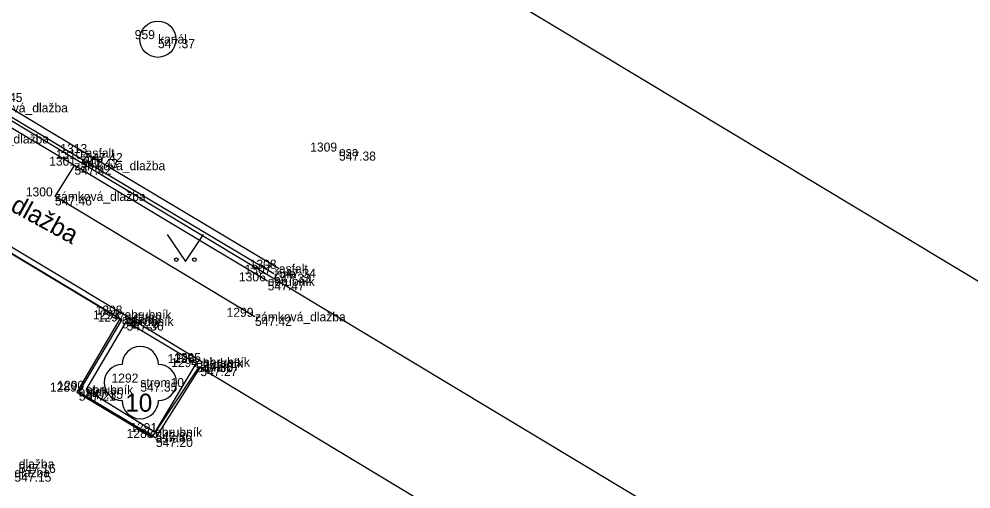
# Model space of a CAD drawing. Extents: x -528274 to -527531, y -1079304 to -1078580.
# Drawn here: x -527787.93 to -527761.62, y -1079117.99 to -1079104.99 of the extents above; entities that cross this region are included whole.
import ezdxf

# ---------------------------------------------------------------- set-up
doc = ezdxf.new("R2010")
doc.units = 0
for name, color, linetype in [('BOD_CISLO', 7, 'Continuous'), ('BOD_KOD', 7, 'Continuous'), ('BOD_VYSKA', 7, 'Continuous'), ('BOD_ZNACKA', 7, 'Continuous'), ('g_kanalizace', 7, 'Continuous'), ('g_komunikace', 7, 'Continuous'), ('g_obrubník', 7, 'Continuous'), ('g_vegetace', 7, 'Continuous'), ('g_zpevněná plocha', 7, 'Continuous'), ('katastrální mapa', 7, 'Continuous'), ('Level 1', 7, 'Continuous'), ('Level 26', 7, 'Continuous')]:
    doc.layers.add(name, color=color, linetype=linetype)

# ---------------------------------------------------------------- blocks, each defined once
blk = doc.blocks.new('6.200')
at = {"layer": 'BOD_CISLO'}
blk.add_circle((0, 0), 0.1, dxfattribs=at)
blk = doc.blocks.new('3.130')
at = {"layer": 'BOD_CISLO'}
blk.add_circle((0, 0), 0.0001, dxfattribs=at)
for centre, start, end in [((0, 0.1), 0, 180), ((-0.1, 0), 90, 270), ((0.1, 0), 270, 90), ((0, -0.1), 180, 360)]:
    blk.add_arc(centre, 0.1, start, end, dxfattribs=at)
blk = doc.blocks.new('3.140')
at = {"layer": 'BOD_CISLO'}
blk.add_lwpolyline([(-0.1, 0.15), (0, 0), (0.1, 0.15)], dxfattribs=at)
for centre in [(-0.05, 0.01), (0.05, 0.01)]:
    blk.add_circle(centre, 0.01, dxfattribs=at)

msp = doc.modelspace()

# ---------------------------------------------------------------- linework, layer by layer
at = {"layer": 'BOD_ZNACKA'}
for p, q in [((-527784.09, -1079105.55), (-527784.09, -1079105.55)), ((-527786.09, -1079108.7), (-527786.09, -1079108.7)), ((-527779.09, -1079108.66), (-527779.09, -1079108.66)), ((-527786.4, -1079109.05), (-527786.4, -1079109.05)), ((-527786.22, -1079108.86), (-527786.22, -1079108.86)), ((-527786.94, -1079109.9), (-527786.94, -1079109.9)), ((-527780.75, -1079111.9), (-527780.75, -1079111.9)), ((-527780.89, -1079112.04), (-527780.89, -1079112.04)), ((-527781.06, -1079112.25), (-527781.06, -1079112.25)), ((-527785.02, -1079113.17), (-527785.02, -1079113.17)), ((-527781.41, -1079113.23), (-527781.41, -1079113.23)), ((-527785.09, -1079113.3), (-527785.09, -1079113.3)), ((-527784.96, -1079113.36), (-527784.96, -1079113.36)), ((-527783.04, -1079114.51), (-527783.04, -1079114.51)), ((-527782.85, -1079114.48), (-527782.85, -1079114.48)), ((-527782.92, -1079114.62), (-527782.92, -1079114.62)), ((-527784.58, -1079115.05), (-527784.58, -1079115.05)), ((-527786.28, -1079115.3), (-527786.28, -1079115.3)), ((-527786.08, -1079115.25), (-527786.08, -1079115.25)), ((-527784.17, -1079116.42), (-527784.17, -1079116.42)), ((-527784.15, -1079116.58), (-527784.15, -1079116.58))]:
    msp.add_line(p, q, dxfattribs=at)
at = {"layer": 'g_komunikace'}
for points in [[(-527780.892, -1079112.041), (-527786.224, -1079108.857), (-527788.97, -1079107.221), (-527798.424, -1079101.633), (-527809.859, -1079094.925), (-527820.028, -1079089.027)], [(-527795.734, -1079106.9), (-527785.089, -1079113.303), (-527786.282, -1079115.304), (-527784.148, -1079116.581), (-527782.92, -1079114.618)]]:
    msp.add_lwpolyline(points, dxfattribs=at)
at = {"layer": 'g_obrubník'}
for points in [[(-527781.061, -1079112.246), (-527786.403, -1079109.045), (-527789.09, -1079107.448), (-527798.572, -1079101.839), (-527809.976, -1079095.102), (-527820.148, -1079089.259)], [(-527819.747, -1079098.656), (-527815.037, -1079095.039), (-527810.686, -1079097.705), (-527808.476, -1079099.047), (-527797.86, -1079105.467), (-527795.68, -1079106.766), (-527785.022, -1079113.17), (-527782.853, -1079114.48)]]:
    msp.add_lwpolyline(points, dxfattribs=at)
msp.add_lwpolyline([(-527783.039, -1079114.508), (-527784.174, -1079116.42), (-527786.077, -1079115.247), (-527784.963, -1079113.356)], close=True, dxfattribs=at)
at = {"layer": 'g_zpevněná plocha'}
for points in [[(-527819.943, -1079088.882), (-527809.744, -1079094.756), (-527798.324, -1079101.447), (-527788.857, -1079107.037), (-527786.093, -1079108.695), (-527780.745, -1079111.898)], [(-527781.414, -1079113.23), (-527786.936, -1079109.902), (-527786.403, -1079109.045)]]:
    msp.add_lwpolyline(points, dxfattribs=at)
at = {"layer": 'katastrální mapa'}
for p, q in [((-527778.19, -1079102.14), (-527749.4, -1079119.49)), ((-527795.69, -1079103.27), (-527760.25, -1079124.58)), ((-527795.8, -1079106.86), (-527785.15, -1079113.29)), ((-527785.15, -1079113.29), (-527786.33, -1079115.31)), ((-527784.25, -1079116.56), (-527782.95, -1079114.61)), ((-527782.95, -1079114.61), (-527772.25, -1079121.07)), ((-527786.33, -1079115.31), (-527784.25, -1079116.56))]:
    msp.add_line(p, q, dxfattribs=at)
at = {"layer": 'Level 1'}
for p, q in [((-527784.094, -1079105.554), (-527784.094, -1079105.554)), ((-527786.093, -1079108.695), (-527786.093, -1079108.695)), ((-527779.091, -1079108.657), (-527779.091, -1079108.657)), ((-527786.403, -1079109.045), (-527786.403, -1079109.045)), ((-527786.224, -1079108.857), (-527786.224, -1079108.857)), ((-527786.936, -1079109.902), (-527786.936, -1079109.902)), ((-527780.745, -1079111.898), (-527780.745, -1079111.898)), ((-527780.892, -1079112.041), (-527780.892, -1079112.041)), ((-527781.061, -1079112.246), (-527781.061, -1079112.246)), ((-527785.022, -1079113.17), (-527785.022, -1079113.17)), ((-527781.414, -1079113.23), (-527781.414, -1079113.23)), ((-527785.089, -1079113.303), (-527785.089, -1079113.303)), ((-527784.963, -1079113.356), (-527784.963, -1079113.356)), ((-527783.039, -1079114.508), (-527783.039, -1079114.508)), ((-527782.853, -1079114.48), (-527782.853, -1079114.48)), ((-527782.92, -1079114.618), (-527782.92, -1079114.618)), ((-527784.58, -1079115.048), (-527784.58, -1079115.048)), ((-527786.282, -1079115.304), (-527786.282, -1079115.304)), ((-527786.077, -1079115.247), (-527786.077, -1079115.247)), ((-527784.174, -1079116.42), (-527784.174, -1079116.42)), ((-527784.148, -1079116.581), (-527784.148, -1079116.581))]:
    msp.add_line(p, q, dxfattribs=at)
at = {"layer": 'Level 26'}
for p, q in [((-527784.09, -1079105.55), (-527784.09, -1079105.55)), ((-527786.09, -1079108.7), (-527786.09, -1079108.7)), ((-527779.09, -1079108.66), (-527779.09, -1079108.66)), ((-527786.4, -1079109.05), (-527786.4, -1079109.05)), ((-527786.22, -1079108.86), (-527786.22, -1079108.86)), ((-527786.94, -1079109.9), (-527786.94, -1079109.9)), ((-527780.75, -1079111.9), (-527780.75, -1079111.9)), ((-527780.89, -1079112.04), (-527780.89, -1079112.04)), ((-527781.06, -1079112.25), (-527781.06, -1079112.25)), ((-527785.02, -1079113.17), (-527785.02, -1079113.17)), ((-527781.41, -1079113.23), (-527781.41, -1079113.23)), ((-527785.09, -1079113.3), (-527785.09, -1079113.3)), ((-527784.96, -1079113.36), (-527784.96, -1079113.36)), ((-527783.04, -1079114.51), (-527783.04, -1079114.51)), ((-527782.85, -1079114.48), (-527782.85, -1079114.48)), ((-527782.92, -1079114.62), (-527782.92, -1079114.62)), ((-527784.58, -1079115.05), (-527784.58, -1079115.05)), ((-527786.28, -1079115.3), (-527786.28, -1079115.3)), ((-527786.08, -1079115.25), (-527786.08, -1079115.25)), ((-527784.17, -1079116.42), (-527784.17, -1079116.42)), ((-527784.15, -1079116.58), (-527784.15, -1079116.58))]:
    msp.add_line(p, q, dxfattribs=at)

# ---------------------------------------------------------------- block references
at = {"layer": 'g_kanalizace', "xscale": 5, "yscale": 5}
msp.add_blockref('6.200', (-527784.094, -1079105.554), dxfattribs=at)
at = {"layer": 'g_vegetace', "xscale": 5, "yscale": 5}
for name, p in [('3.140', (-527783.334, -1079111.699)), ('3.130', (-527784.58, -1079115.048))]:
    msp.add_blockref(name, p, dxfattribs=at)

# ---------------------------------------------------------------- texts
at = {"layer": 'BOD_CISLO'}
for s, p in [('959', (-527784.734, -1079105.55)), ('1313', (-527786.791, -1079108.7)), ('1309', (-527779.885, -1079108.66)), ('1301', (-527787.099, -1079109.05)), ('1310', (-527786.919, -1079108.86)), ('1300', (-527787.745, -1079109.9)), ('1308', (-527781.557, -1079111.9)), ('1307', (-527781.699, -1079112.04)), ('1306', (-527781.855, -1079112.25)), ('1298', (-527785.817, -1079113.17)), ('1299', (-527782.195, -1079113.23)), ('1293', (-527785.887, -1079113.3)), ('1297', (-527785.759, -1079113.36)), ('1296', (-527783.825, -1079114.51)), ('1295', (-527783.647, -1079114.48)), ('1294', (-527783.729, -1079114.62)), ('1292', (-527785.377, -1079115.05)), ('1289', (-527787.077, -1079115.3)), ('1290', (-527786.875, -1079115.25)), ('1291', (-527784.859, -1079116.42)), ('1288', (-527784.959, -1079116.58))]:
    msp.add_text(s, height=0.25, dxfattribs=at).set_placement(p)
at = {"layer": 'BOD_KOD'}
for s, p in [('kanál', (-527784.09, -1079105.675)), ('zámková_dlažba', (-527789.09, -1079107.575)), ('zámková_dlažba', (-527789.61, -1079108.435)), ('žula', (-527786.22, -1079108.985)), ('asfalt', (-527786.09, -1079108.825)), ('osa', (-527779.09, -1079108.785)), ('zámková_dlažba', (-527786.4, -1079109.175)), ('zámková_dlažba', (-527786.94, -1079110.025)), ('žula', (-527780.89, -1079112.165)), ('asfalt', (-527780.75, -1079112.025)), ('obrubník', (-527781.06, -1079112.375)), ('obrubník', (-527785.02, -1079113.295)), ('asfalt', (-527785.09, -1079113.425)), ('obrubník', (-527784.96, -1079113.485)), ('zámková_dlažba', (-527781.41, -1079113.355)), ('obrubník', (-527782.85, -1079114.605)), ('obrubník', (-527783.04, -1079114.635)), ('asfalt', (-527782.92, -1079114.745)), ('obrubník', (-527786.08, -1079115.375)), ('strom10', (-527784.58, -1079115.175)), ('asfalt', (-527786.28, -1079115.425)), ('obrubník', (-527784.17, -1079116.545)), ('asfalt', (-527784.15, -1079116.705)), ('dlažba', (-527787.94, -1079117.425)), ('dlažba', (-527788.06, -1079117.665))]:
    msp.add_text(s, height=0.25, dxfattribs=at).set_placement(p)
at = {"layer": 'BOD_VYSKA'}
for s, p in [('547.37', (-527784.09, -1079105.8)), ('547.45', (-527788.86, -1079107.29)), ('547.42', (-527786.09, -1079108.95)), ('547.38', (-527779.09, -1079108.91)), ('547.42', (-527786.4, -1079109.3)), ('547.43', (-527786.22, -1079109.11)), ('547.46', (-527786.94, -1079110.15)), ('547.34', (-527780.75, -1079112.15)), ('547.33', (-527780.89, -1079112.29)), ('547.47', (-527781.06, -1079112.5)), ('547.38', (-527785.02, -1079113.42)), ('547.42', (-527781.41, -1079113.48)), ('547.29', (-527785.09, -1079113.55)), ('547.36', (-527784.96, -1079113.61)), ('547.36', (-527783.04, -1079114.76)), ('547.37', (-527782.85, -1079114.73)), ('547.27', (-527782.92, -1079114.87)), ('547.35', (-527784.58, -1079115.3)), ('547.21', (-527786.28, -1079115.55)), ('547.35', (-527786.08, -1079115.5)), ('547.36', (-527784.17, -1079116.67)), ('547.20', (-527784.15, -1079116.83)), ('547.16', (-527787.94, -1079117.55)), ('547.15', (-527788.06, -1079117.79))]:
    msp.add_text(s, height=0.25, dxfattribs=at).set_placement(p)
at = {"layer": 'g_vegetace'}
msp.add_text('10', height=0.5, dxfattribs=at).set_placement((-527784.994, -1079115.856))
at = {"layer": 'g_zpevněná plocha'}
msp.add_text('zámková dlažba', height=0.5, rotation=331.3619, dxfattribs=at).set_placement((-527790.708, -1079108.914))

doc.saveas('drawing.dxf')
